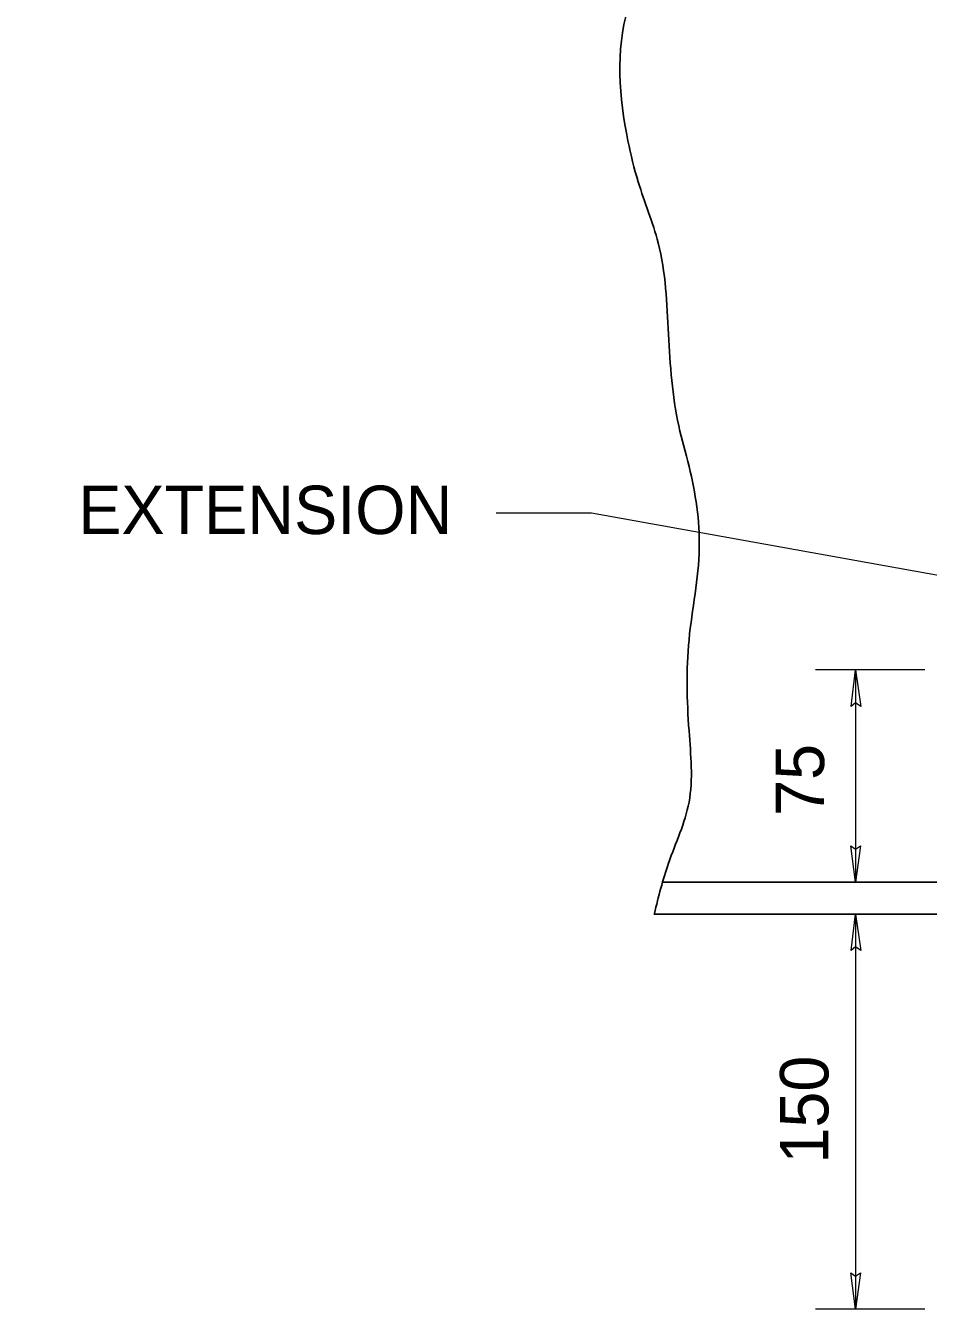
# Model space of a CAD drawing. Extents: x 312583 to 312854, y 144419 to 144597.
# Drawn here: x 312715.13 to 312729.3, y 144460.17 to 144480.33 of the extents above; entities that cross this region are included whole.
import ezdxf

# ---------------------------------------------------------------- set-up
doc = ezdxf.new("R2010")
doc.units = 0
doc.header["$LTSCALE"] = 0.3
doc.layers.add('1', color=7, linetype='Continuous', lineweight=25)

msp = doc.modelspace()

# ---------------------------------------------------------------- linework, layer by layer
at = {"layer": '1', "lineweight": 13}
for p, q in [((312722.5122, 144472.6805), (312724.0072, 144472.6805)), ((312724.0072, 144472.6805), (312736.4732, 144470.4419)), ((312729.2435, 144470.2119), (312727.5262, 144470.2119)), ((312728.1548, 144470.2119), (312728.1548, 144466.8769)), ((312728.1548, 144466.3785), (312728.1548, 144460.1685)), ((312729.2435, 144460.1685), (312727.5262, 144460.1685))]:
    msp.add_line(p, q, dxfattribs=at)
at = {"layer": '1'}
for p, q in [((312725.1265, 144466.8769), (312735.9748, 144466.8769)), ((312724.9885, 144466.3785), (312736.4732, 144466.3785))]:
    msp.add_line(p, q, dxfattribs=at)
at = {"layer": '1', "lineweight": 13}
for points in [[(312728.0858, 144469.6369), (312728.1548, 144470.2119), (312728.2392, 144469.6369), (312728.1548, 144469.6982)], [(312728.2315, 144467.4519), (312728.1548, 144466.8769), (312728.0782, 144467.4519), (312728.1548, 144467.3982)], [(312728.0858, 144465.8035), (312728.1548, 144466.3785), (312728.2392, 144465.8035), (312728.1548, 144465.8649)], [(312728.2315, 144460.7435), (312728.1548, 144460.1685), (312728.0782, 144460.7435), (312728.1548, 144460.6899)]]:
    msp.add_lwpolyline(points, close=True, dxfattribs=at)
at = {"layer": '1'}
msp.add_spline([(312715.1522, 144518.2129), (312715.1522, 144517.3465), (312715.6352, 144515.9052), (312716.2715, 144515.1079), (312716.9078, 144514.3105), (312718.0272, 144513.1912), (312718.8245, 144512.0719), (312719.3075, 144510.6382), (312719.7828, 144509.3579), (312720.5878, 144507.7632), (312721.3852, 144505.8389), (312721.7072, 144504.0832), (312721.8605, 144501.5302), (312722.6655, 144500.2499), (312723.4628, 144499.1305), (312724.5822, 144497.3749), (312725.3795, 144495.7725), (312726.1768, 144494.4999), (312726.6598, 144493.3805), (312726.8132, 144492.2612), (312726.8132, 144490.5055), (312726.8132, 144488.4279), (312726.0158, 144485.5529), (312725.8548, 144484.9089), (312725.0575, 144482.6779), (312724.7432, 144481.0755), (312724.5822, 144480.6002), (312724.5822, 144478.5225), (312724.7432, 144477.8785), (312725.0575, 144476.9202), (312725.2185, 144475.4865), (312725.3795, 144474.0452), (312725.5405, 144473.4089), (312725.7015, 144472.1285), (312725.5405, 144470.6872), (312725.5405, 144469.2535), (312725.5405, 144468.1342), (312725.2185, 144467.1759), (312724.9962, 144466.3862)], degree=3, dxfattribs=at)

# ---------------------------------------------------------------- texts
msp.add_text('EXTENSION', height=0.76, dxfattribs=at).set_placement((312715.9513, 144472.3473))
for s, p in [('75', (312727.6616, 144467.9198)), ('150', (312727.7287, 144462.4578))]:
    msp.add_text(s, height=0.76, rotation=90, dxfattribs=at).set_placement(p)

doc.saveas('drawing.dxf')
